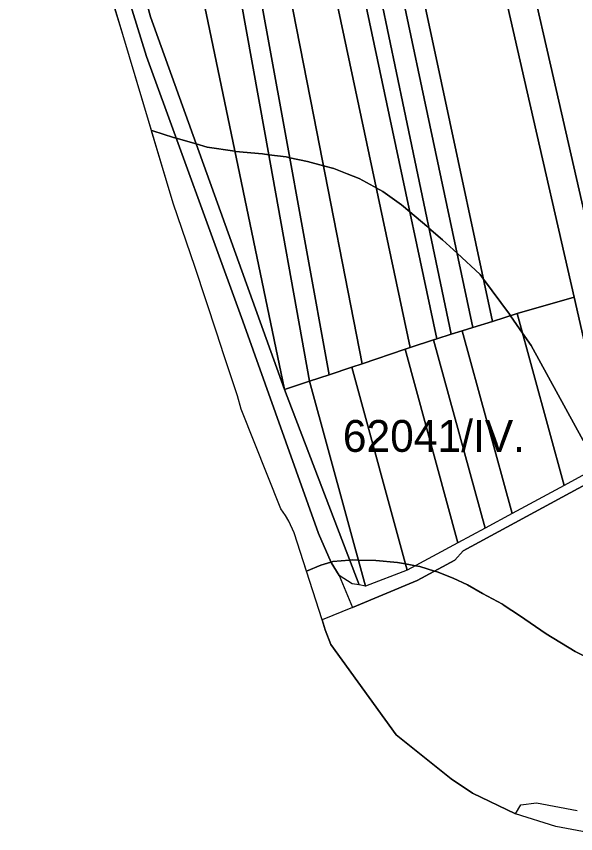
# Model space of a CAD drawing. Extents: x -521939 to -516426, y -1197857 to -1189551.
# Drawn here: x -519945.5 to -519681.9, y -1194134.6 to -1193749.4 of the extents above; entities that cross this region are included whole.
import ezdxf

# ---------------------------------------------------------------- set-up
doc = ezdxf.new("R2010")
doc.units = 0
for name, color, linetype in [('95560013', 7, 'Continuous'), ('95610013', 7, 'Continuous'), ('95640013', 7, 'Continuous'), ('95660013', 7, 'Continuous')]:
    doc.layers.add(name, color=color, linetype=linetype)

msp = doc.modelspace()

# ---------------------------------------------------------------- linework, layer by layer
at = {"layer": '95560013'}
for points in [[(-519652.7, -1193951.75), (-519692.33, -1193778.37), (-519736.87, -1193583.51), (-519772.58, -1193427.28), (-519739.99, -1193421.5), (-519622.78, -1193935.57), (-519633.36, -1193941.29)], [(-519652.7, -1193951.75), (-519657.74, -1193954.5), (-519665.13, -1193958.51), (-519682.62, -1193881.84), (-519704.7, -1193785.08), (-519745.25, -1193607.38), (-519785.8, -1193429.68), (-519772.58, -1193427.28), (-519736.87, -1193583.51), (-519692.33, -1193778.37)], [(-519682.62, -1193881.84), (-519709.36, -1193889.56), (-519721.06, -1193893.21), (-519745.1, -1193780.79), (-519781.84, -1193608.98), (-519818.92, -1193435.58), (-519785.8, -1193429.68), (-519745.25, -1193607.38), (-519704.7, -1193785.08)], [(-519818.92, -1193435.58), (-519781.84, -1193608.98), (-519745.1, -1193780.79), (-519721.06, -1193893.21), (-519730.3, -1193896.09), (-519753.21, -1193788.16), (-519790.24, -1193613.71), (-519827.72, -1193437.14)], [(-519845.18, -1193440.25), (-519836.7, -1193438.75), (-519798.79, -1193620.42), (-519762.71, -1193793.34), (-519740.6, -1193899.3), (-519747.32, -1193901.39), (-519769.7, -1193795.93), (-519807.44, -1193618.09)], [(-519730.3, -1193896.09), (-519735.29, -1193897.65), (-519740.6, -1193899.3), (-519762.71, -1193793.34), (-519798.79, -1193620.42), (-519836.7, -1193438.75), (-519827.72, -1193437.14), (-519790.24, -1193613.71), (-519753.21, -1193788.16)], [(-519873.97, -1193445.38), (-519858.21, -1193442.6), (-519821.14, -1193617.12), (-519784.07, -1193791.64), (-519759.87, -1193905.57), (-519762.19, -1193906.35), (-519782.5, -1193913.17), (-519805.28, -1193796.67), (-519839.45, -1193621.92)], [(-519858.21, -1193442.6), (-519845.18, -1193440.25), (-519807.44, -1193618.09), (-519769.7, -1193795.93), (-519747.32, -1193901.39), (-519748.79, -1193901.87), (-519759.87, -1193905.57), (-519784.07, -1193791.64), (-519821.14, -1193617.12)], [(-519892.63, -1193448.74), (-519883.67, -1193447.13), (-519851.71, -1193623.05), (-519819.75, -1193798.97), (-519798.06, -1193918.36), (-519807.25, -1193921.42), (-519828.25, -1193805.16), (-519860.44, -1193626.95)], [(-519873.97, -1193445.38), (-519839.45, -1193621.92), (-519805.28, -1193796.67), (-519782.5, -1193913.17), (-519787.39, -1193914.81), (-519798.06, -1193918.36), (-519819.75, -1193798.97), (-519851.71, -1193623.05), (-519883.67, -1193447.13)], [(-519917.37, -1193453.09), (-519892.63, -1193448.74), (-519860.44, -1193626.95), (-519828.25, -1193805.16), (-519807.25, -1193921.42), (-519819.1, -1193925.23), (-519843.45, -1193808.24), (-519880.64, -1193629.56)], [(-519917.37, -1193453.09), (-519880.64, -1193629.56), (-519843.45, -1193808.24), (-519819.1, -1193925.23), (-519882.21, -1193749.64), (-519908.38, -1193653.77), (-519903.71, -1193641.87), (-519919.19, -1193557.82), (-519929.74, -1193455.31)], [(-519665.13, -1193958.51), (-519687.29, -1193970.52), (-519709.36, -1193889.56), (-519682.62, -1193881.84)], [(-519709.36, -1193889.56), (-519687.29, -1193970.52), (-519711.79, -1193983.75), (-519735.29, -1193897.65), (-519730.3, -1193896.09), (-519721.06, -1193893.21)], [(-519735.29, -1193897.65), (-519711.79, -1193983.75), (-519724.57, -1193990.65), (-519748.79, -1193901.87), (-519747.32, -1193901.39), (-519740.6, -1193899.3)], [(-519762.19, -1193906.35), (-519759.87, -1193905.57), (-519748.79, -1193901.87), (-519724.57, -1193990.65), (-519737.33, -1193997.55)], [(-519737.33, -1193997.55), (-519761.2, -1194010.43), (-519787.39, -1193914.81), (-519782.5, -1193913.17), (-519762.19, -1193906.35)], [(-519761.2, -1194010.43), (-519780.88, -1194018.05), (-519807.25, -1193921.42), (-519798.06, -1193918.36), (-519787.39, -1193914.81)], [(-519807.25, -1193921.42), (-519780.88, -1194018.05), (-519783.96, -1194017.34), (-519819.1, -1193925.23)]]:
    msp.add_lwpolyline(points, close=True, dxfattribs=at)
at = {"layer": '95610013'}
for points in [[(-519663.79, -1193962.87), (-519734.84, -1194001.31), (-519738.79, -1194005.72), (-519756.49, -1194015.3), (-519786.98, -1194028.03)], [(-519786.98, -1194028.03), (-519801.37, -1194033.88)], [(-519801.37, -1194033.88), (-519799.88, -1194038.54), (-519797.27, -1194045.4)], [(-519797.27, -1194045.4), (-519766.42, -1194087.98), (-519740.5, -1194108.83)], [(-519740.5, -1194108.83), (-519730.5, -1194115.53), (-519710.16, -1194125.22)], [(-519710.16, -1194125.22), (-519707.66, -1194121.08)], [(-519707.66, -1194121.08), (-519700.28, -1194120.14)], [(-519700.28, -1194120.14), (-519681.19, -1194123.7)]]:
    msp.add_lwpolyline(points, dxfattribs=at)
at = {"layer": '95640013'}
msp.add_lwpolyline([(-519929.74, -1193455.31), (-519919.19, -1193557.82), (-519903.71, -1193641.87), (-519908.38, -1193653.77), (-519882.21, -1193749.64), (-519819.1, -1193925.23), (-519783.96, -1194017.34), (-519787.2, -1194016.94), (-519793.25, -1194013), (-519797.12, -1194006.88), (-519803, -1193993.09), (-519838.68, -1193893.05), (-519884.16, -1193768.38), (-519903.84, -1193704.77), (-519915.89, -1193656.93), (-519925.96, -1193608.64), (-519935.92, -1193546.31), (-519942.75, -1193485.33), (-519943.72, -1193466.02), (-519945.47, -1193462.14), (-519943.76, -1193457.81)], close=True, dxfattribs=at)
for points in [[(-519903.84, -1193704.77), (-519884.16, -1193768.38), (-519838.68, -1193893.05), (-519803, -1193993.09), (-519797.12, -1194006.88), (-519793.25, -1194013), (-519786.98, -1194028.03), (-519801.37, -1194033.88), (-519814.49, -1193992.92), (-519816.99, -1193987.28), (-519818.64, -1193984.6), (-519820.78, -1193981.48), (-519839.55, -1193934.52), (-519841.31, -1193928.23), (-519847.64, -1193908.92), (-519850.99, -1193898.71), (-519861.11, -1193867.84), (-519871.53, -1193837.56), (-519895.34, -1193757.93), (-519916.08, -1193688.59)], [(-519665.13, -1193958.51), (-519687.29, -1193970.52)], [(-519786.98, -1194028.03), (-519756.49, -1194015.3), (-519738.79, -1194005.72), (-519734.84, -1194001.31), (-519663.79, -1193962.87)], [(-519687.29, -1193970.52), (-519711.79, -1193983.75)], [(-519711.79, -1193983.75), (-519724.57, -1193990.65)], [(-519724.57, -1193990.65), (-519737.33, -1193997.55)], [(-519737.33, -1193997.55), (-519761.2, -1194010.43)], [(-519783.96, -1194017.34), (-519787.2, -1194016.94), (-519793.25, -1194013)], [(-519793.25, -1194013), (-519786.98, -1194028.03)], [(-519761.2, -1194010.43), (-519780.88, -1194018.05)], [(-519780.88, -1194018.05), (-519783.96, -1194017.34)], [(-519673.57, -1194134.61), (-519691.18, -1194131.21), (-519710.16, -1194125.22), (-519707.66, -1194121.08), (-519700.28, -1194120.14), (-519681.19, -1194123.7)]]:
    msp.add_lwpolyline(points, dxfattribs=at)
at = {"layer": '95660013'}
for points in [[(-519895.34, -1193757.93), (-519900.39, -1193741.04)], [(-519678.35, -1193949.36), (-519702.81, -1193904.62), (-519706.86, -1193898.73), (-519712.49, -1193890.54), (-519713.01, -1193889.78), (-519725.33, -1193873.26), (-519726.92, -1193871.12), (-519737.73, -1193861.1), (-519744.54, -1193854.78), (-519751.05, -1193849.2), (-519752, -1193848.39), (-519760.03, -1193841.51), (-519763.89, -1193838.2), (-519772.7, -1193832.06), (-519775.85, -1193830.32), (-519777.05, -1193829.66), (-519783.83, -1193825.92), (-519789.49, -1193823.66), (-519795.77, -1193821.16), (-519800.75, -1193819.86), (-519808.17, -1193817.92), (-519816.64, -1193816.07), (-519818.26, -1193815.72), (-519826.54, -1193814.65), (-519829.44, -1193814.27), (-519842.13, -1193813.11), (-519842.45, -1193813.06), (-519855.46, -1193811.08), (-519860.67, -1193809.58), (-519870.13, -1193806.85), (-519871.34, -1193806.5), (-519881.11, -1193803.47), (-519881.79, -1193803.26), (-519895.34, -1193757.93)], [(-519871.53, -1193837.56), (-519881.39, -1193804.57), (-519881.75, -1193803.38), (-519881.75, -1193803.38), (-519881.79, -1193803.26), (-519881.11, -1193803.47), (-519871.34, -1193806.5), (-519870.13, -1193806.85), (-519860.67, -1193809.58), (-519855.46, -1193811.08), (-519842.45, -1193813.06), (-519842.13, -1193813.11), (-519829.44, -1193814.27), (-519826.54, -1193814.65), (-519818.26, -1193815.72), (-519816.64, -1193816.07), (-519808.17, -1193817.92), (-519800.75, -1193819.86), (-519795.77, -1193821.16), (-519789.49, -1193823.66), (-519783.83, -1193825.92), (-519777.05, -1193829.66), (-519775.85, -1193830.32), (-519772.7, -1193832.06), (-519763.89, -1193838.2), (-519760.03, -1193841.51), (-519752, -1193848.39), (-519751.05, -1193849.2), (-519744.54, -1193854.78), (-519737.73, -1193861.1), (-519726.92, -1193871.12), (-519725.33, -1193873.26), (-519713.01, -1193889.78), (-519712.49, -1193890.54), (-519706.86, -1193898.73), (-519702.81, -1193904.62), (-519678.35, -1193949.36)], [(-519676.11, -1194051.68), (-519682.02, -1194048.78), (-519695.81, -1194040.44), (-519708.27, -1194031.8), (-519715.53, -1194027.03), (-519716.39, -1194026.47), (-519725.77, -1194021.37), (-519732.84, -1194017.43), (-519739.57, -1194014.18), (-519747.1, -1194011.29), (-519748.36, -1194010.9), (-519755.33, -1194008.74), (-519757.36, -1194008.36), (-519762.01, -1194007.48), (-519765.76, -1194006.77), (-519776.08, -1194005.84), (-519784.26, -1194005.67), (-519786.86, -1194005.61), (-519788.39, -1194005.74), (-519796.36, -1194006.42), (-519797.21, -1194006.67), (-519801.93, -1194008.04), (-519808.7, -1194010.98), (-519814.49, -1193992.92), (-519816.99, -1193987.28), (-519818.64, -1193984.6), (-519820.78, -1193981.48), (-519839.55, -1193934.52), (-519841.31, -1193928.23), (-519847.64, -1193908.92), (-519850.99, -1193898.71), (-519861.11, -1193867.84), (-519871.53, -1193837.56)], [(-519673.57, -1194134.61), (-519691.18, -1194131.21), (-519710.16, -1194125.22), (-519730.5, -1194115.53), (-519740.5, -1194108.83), (-519766.42, -1194087.98), (-519797.27, -1194045.4), (-519799.88, -1194038.54), (-519801.37, -1194033.88), (-519808.7, -1194010.98), (-519801.93, -1194008.04), (-519797.21, -1194006.67), (-519796.36, -1194006.42), (-519788.39, -1194005.74), (-519786.86, -1194005.61), (-519784.26, -1194005.67), (-519776.08, -1194005.84), (-519765.76, -1194006.77), (-519762.01, -1194007.48), (-519757.36, -1194008.36), (-519755.33, -1194008.74), (-519748.36, -1194010.9), (-519747.1, -1194011.29), (-519739.57, -1194014.18), (-519732.84, -1194017.43), (-519725.77, -1194021.37), (-519716.39, -1194026.47), (-519715.53, -1194027.03), (-519708.27, -1194031.8), (-519695.81, -1194040.44), (-519682.02, -1194048.78), (-519676.11, -1194051.68)]]:
    msp.add_lwpolyline(points, dxfattribs=at)

# ---------------------------------------------------------------- texts
msp.add_text('62041/IV.', height=15, rotation=360, dxfattribs=at).set_placement((-519791.59, -1193954.69))

doc.saveas('drawing.dxf')
